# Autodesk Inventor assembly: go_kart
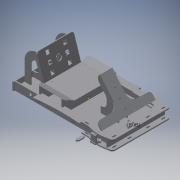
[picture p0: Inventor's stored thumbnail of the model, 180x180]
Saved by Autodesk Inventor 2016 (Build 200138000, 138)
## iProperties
Created: 2017-06
Part Number: go_kart
Document SubType Name: Assembly
Designer: laboratorioesan
Author: laboratorioesan
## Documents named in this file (24)
- C:\Users\laboratorioesan\Desktop\Proyecto final\go_kart.iam
- C:\Users\laboratorioesan\Desktop\Proyecto final\marco_lateral.ipt
- C:\Users\laboratorioesan\Desktop\Proyecto final\Part3.ipt
- C:\Users\laboratorioesan\Desktop\Proyecto final\marco_frontal.ipt
- C:\Users\laboratorioesan\Desktop\Proyecto final\base_marco.ipt
- C:\Users\laboratorioesan\Desktop\Proyecto final\transversal_marco.ipt
- C:\Users\laboratorioesan\Desktop\Proyecto final\asiento_base.ipt
- C:\Users\laboratorioesan\Desktop\Proyecto final\asiento_lateral.ipt
- C:\Users\laboratorioesan\Desktop\Proyecto final\fenders.ipt
- C:\Users\laboratorioesan\Desktop\Proyecto final\nervio_fender.ipt
- C:\Users\laboratorioesan\Desktop\Proyecto final\marco_frontal_1.ipt
- C:\Users\laboratorioesan\Desktop\Proyecto final\mascara_frontal.ipt
- C:\Users\laboratorioesan\Desktop\Proyecto final\uniones_mascara.ipt
- C:\Users\laboratorioesan\Desktop\Proyecto final\acople_nuevo.ipt
- C:\Users\laboratorioesan\Desktop\Proyecto final\acople_union_1.ipt
- C:\Users\laboratorioesan\Desktop\Proyecto final\acople_eje.ipt
- C:\Users\laboratorioesan\Desktop\Proyecto final\frontal_timon_estructura.ipt
- C:\Users\laboratorioesan\Desktop\Proyecto final\lateral_timon_estructura.ipt
- C:\Users\laboratorioesan\Desktop\Proyecto final\union_mascara.ipt
- C:\Users\laboratorioesan\Desktop\Proyecto final\espaldar_asiento.ipt
- C:\Users\laboratorioesan\Desktop\Proyecto final\espaldar_union_vertical.ipt
- C:\Users\laboratorioesan\Desktop\Proyecto final\chumaceras.ipt
- C:\Users\laboratorioesan\Desktop\Proyecto final\Soporte_eje_pequeño.ipt
- C:\Users\laboratorioesan\Desktop\Proyecto final\acople_union_2.ipt
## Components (35 placed, 23 different names)
1. marco_lateral:1 — Flush:1, Mate:4, Mate:6, Mate:7, Flush:2, Flush:3, Mate:14, Mate:15, Mate:22, Mate:23, Mate:24, Mate:25, Mate:26, Mate:27, Mate:28
2. Part3:1 — Flush:1, Mate:1, Mate:2, Mate:3
3. marco_lateral:4 — Mate:1, Mate:2, Mate:3, Mate:5, Mate:8, Mate:9, Mate:13, Flush:6, Flush:7, Mate:19
4. marco_frontal:1 — Mate:4, Mate:5, Mate:6, Mate:7, Mate:8, Mate:9, Flush:20, Mate:50, Mate:51
5. base_marco:1 — Flush:2, Flush:8, Mate:40, Flush:18, Mate:46
6. transversal_marco:1 — Flush:3, Flush:5, Mate:17, Mate:18
7. transversal_marco:2 — Mate:13, Mate:14, Mate:15, Flush:4, Mate:16, Mate:29, Mate:30, Mate:49
8. asiento_base:1 — Flush:4, Flush:17
9. asiento_lateral:1 — Flush:5
10. asiento_lateral:2 — Mate:16, Mate:17, Mate:18
11. fenders:1 — Flush:6, Mate:20, Mate:21
12. nervio_fender:1 — Flush:7
13. nervio_fender:2 — Mate:19, Mate:20, Mate:21
14. nervio_fender:3 — Mate:22, Mate:23, Mate:24
15. nervio_fender:4 — Mate:25, Mate:26, Mate:27
16. fenders:2 — Mate:28, Mate:29, Mate:30
17. marco_frontal_1:1 — Flush:8, Flush:9, Mate:31, Mate:32, Mate:33
18. mascara_frontal:1 — Flush:9, Flush:12, Mate:43
19. mascara_frontal:2 — Mate:31, Mate:32, Mate:33, Flush:10, Flush:11, Mate:44, Mate:45
20. uniones_mascara:1 — Flush:10
21. acople_nuevo:1 — Flush:11, Flush:12, Mate:34, Mate:35, Mate:36
22. acople_union_1:1 — Mate:34, Mate:35, Mate:36, Mate:37, Mate:38, Mate:39
23. acople_nuevo:2 — Mate:37, Mate:38, Mate:39
24. acople_eje:1
25. frontal_timon_estructura:1 — Flush:16, Mate:41, Mate:42, Flush:19
26. lateral_timon_estructura:1 — Flush:16
27. lateral_timon_estructura:2 — Mate:40, Mate:41, Mate:42
28. union_mascara:1 — Mate:43, Mate:44, Mate:45
29. espaldar_asiento:1 — Flush:17, Mate:47, Mate:48
30. espaldar_union_vertical:1 — Flush:18
31. espaldar_union_vertical:2 — Mate:46, Mate:47, Mate:48
32. chumaceras:1 — Flush:19
33. Soporte_eje_pequeño:1 — Flush:20
34. Soporte_eje_pequeño:2 — Mate:49, Mate:50, Mate:51
35. acople_union_2:1
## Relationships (65: Mate 48, Flush 17)
- Flush:1: marco_lateral:1 ↔ Part3:1
- Mate:1: Part3:1 ↔ marco_lateral:4
- Mate:2: Part3:1 ↔ marco_lateral:4
- Mate:3: Part3:1 ↔ marco_lateral:4
- Mate:4: marco_lateral:1 ↔ marco_frontal:1
- Mate:5: marco_lateral:4 ↔ marco_frontal:1
- Mate:6: marco_lateral:1 ↔ marco_frontal:1
- Mate:7: marco_lateral:1 ↔ marco_frontal:1
- Mate:8: marco_lateral:4 ↔ marco_frontal:1
- Mate:9: marco_lateral:4 ↔ marco_frontal:1
- Flush:2: marco_lateral:1 ↔ base_marco:1
- Flush:3: marco_lateral:1 ↔ transversal_marco:1
- Mate:13: marco_lateral:4 ↔ transversal_marco:2
- Mate:14: marco_lateral:1 ↔ transversal_marco:2
- Mate:15: marco_lateral:1 ↔ transversal_marco:2
- Flush:4: transversal_marco:2 ↔ asiento_base:1
- Flush:5: transversal_marco:1 ↔ asiento_lateral:1
- Mate:16: transversal_marco:2 ↔ asiento_lateral:2
- Mate:17: transversal_marco:1 ↔ asiento_lateral:2
- Mate:18: transversal_marco:1 ↔ asiento_lateral:2
- Flush:6: marco_lateral:4 ↔ fenders:1
- Flush:7: marco_lateral:4 ↔ nervio_fender:1
- Mate:19: marco_lateral:4 ↔ nervio_fender:2
- Mate:20: fenders:1 ↔ nervio_fender:2
- Mate:21: fenders:1 ↔ nervio_fender:2
- Mate:22: marco_lateral:1 ↔ nervio_fender:3
- Mate:23: marco_lateral:1 ↔ nervio_fender:3
- Mate:24: marco_lateral:1 ↔ nervio_fender:3
- Mate:25: marco_lateral:1 ↔ nervio_fender:4
- Mate:26: marco_lateral:1 ↔ nervio_fender:4
- Mate:27: marco_lateral:1 ↔ nervio_fender:4
- Mate:28: marco_lateral:1 ↔ fenders:2
- Mate:29: transversal_marco:2 ↔ fenders:2
- Mate:30: transversal_marco:2 ↔ fenders:2
- Flush:8: base_marco:1 ↔ marco_frontal_1:1
- Flush:9: marco_frontal_1:1 ↔ mascara_frontal:1
- Mate:31: marco_frontal_1:1 ↔ mascara_frontal:2
- Mate:32: marco_frontal_1:1 ↔ mascara_frontal:2
- Mate:33: marco_frontal_1:1 ↔ mascara_frontal:2
- Flush:10: mascara_frontal:2 ↔ uniones_mascara:1
- Flush:11: mascara_frontal:2 ↔ acople_nuevo:1
- Flush:12: mascara_frontal:1 ↔ acople_nuevo:1
- Mate:34: acople_nuevo:1 ↔ acople_union_1:1
- Mate:35: acople_nuevo:1 ↔ acople_union_1:1
- Mate:36: acople_nuevo:1 ↔ acople_union_1:1
- Mate:37: acople_union_1:1 ↔ acople_nuevo:2
- Mate:38: acople_union_1:1 ↔ acople_nuevo:2
- Mate:39: acople_union_1:1 ↔ acople_nuevo:2
- Flush:16: frontal_timon_estructura:1 ↔ lateral_timon_estructura:1
- Mate:40: base_marco:1 ↔ lateral_timon_estructura:2
- Mate:41: frontal_timon_estructura:1 ↔ lateral_timon_estructura:2
- Mate:42: frontal_timon_estructura:1 ↔ lateral_timon_estructura:2
- Mate:43: mascara_frontal:1 ↔ union_mascara:1
- Mate:44: mascara_frontal:2 ↔ union_mascara:1
- Mate:45: mascara_frontal:2 ↔ union_mascara:1
- Flush:17: asiento_base:1 ↔ espaldar_asiento:1
- Flush:18: base_marco:1 ↔ espaldar_union_vertical:1
- Mate:46: base_marco:1 ↔ espaldar_union_vertical:2
- Mate:47: espaldar_asiento:1 ↔ espaldar_union_vertical:2
- Mate:48: espaldar_asiento:1 ↔ espaldar_union_vertical:2
- Flush:19: frontal_timon_estructura:1 ↔ chumaceras:1
- Flush:20: marco_frontal:1 ↔ Soporte_eje_pequeño:1
- Mate:49: transversal_marco:2 ↔ Soporte_eje_pequeño:2
- Mate:50: marco_frontal:1 ↔ Soporte_eje_pequeño:2
- Mate:51: marco_frontal:1 ↔ Soporte_eje_pequeño:2
